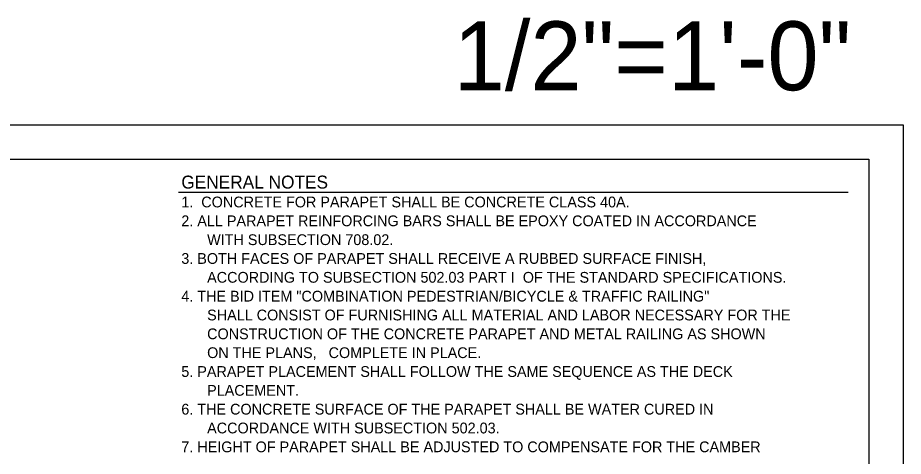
# Model space of a CAD drawing. Extents: x 0 to 68, y 0 to 47.1.
# Drawn here: x 42.27 to 68, y 34.37 to 47.11 of the extents above; entities that cross this region are included whole.
import ezdxf

# ---------------------------------------------------------------- set-up
doc = ezdxf.new("R2010")
doc.units = 0
for name, color, linetype in [('BORDER_ANNO_Cutsheet', 7, 'Continuous'), ('BRDG_ANNO_Anno-Sheet', 7, 'Continuous'), ('BRDG_ANNO_General-Notes', 7, 'Continuous')]:
    doc.layers.add(name, color=color, linetype=linetype)

msp = doc.modelspace()

# ---------------------------------------------------------------- linework, layer by layer
at = {"layer": 'BORDER_ANNO_Cutsheet'}
msp.add_lwpolyline([(0, 44), (68, 44), (68, 0), (0, 0)], close=True, dxfattribs=at)
at = {"layer": 'BRDG_ANNO_Anno-Sheet'}
msp.add_lwpolyline([(3, 43), (67, 43), (67, 1), (3, 1)], close=True, dxfattribs=at)
at = {"layer": 'BRDG_ANNO_General-Notes'}
msp.add_line((46.942, 42.037), (66.402, 42.037), dxfattribs=at)

# ---------------------------------------------------------------- texts
at = {"layer": 'BRDG_ANNO_Anno-Sheet'}
msp.add_text('1/2"=1\'-0"', height=2, dxfattribs=at).set_placement((54.934, 45))
at = {"layer": 'BRDG_ANNO_General-Notes'}
for s, height, p in [('GENERAL NOTES', 0.375, (47.021, 42.147)), ('1.  CONCRETE FOR PARAPET SHALL BE CONCRETE CLASS 40A.', 0.3125, (47.021, 41.6)), ('2. ALL PARAPET REINFORCING BARS SHALL BE EPOXY COATED IN ACCORDANCE', 0.3125, (47.021, 41.053)), ('WITH SUBSECTION 708.02.', 0.3125, (47.771, 40.506)), ('3. BOTH FACES OF PARAPET SHALL RECEIVE A RUBBED SURFACE FINISH,  ', 0.3125, (47.021, 39.96)), ('ACCORDING TO SUBSECTION 502.03 PART I  OF THE STANDARD SPECIFICATIONS.', 0.3125, (47.771, 39.413)), ('4. THE BID ITEM "COMBINATION PEDESTRIAN/BICYCLE & TRAFFIC RAILING"', 0.3125, (47.021, 38.866)), ('SHALL CONSIST OF FURNISHING ALL MATERIAL AND LABOR NECESSARY FOR THE', 0.3125, (47.771, 38.319)), ('CONSTRUCTION OF THE CONCRETE PARAPET AND METAL RAILING AS SHOWN', 0.3125, (47.771, 37.772)), ('ON THE PLANS,   COMPLETE IN PLACE.', 0.3125, (47.771, 37.225)), ('5. PARAPET PLACEMENT SHALL FOLLOW THE SAME SEQUENCE AS THE DECK', 0.3125, (47.021, 36.678)), ('PLACEMENT.', 0.3125, (47.771, 36.131)), ('6. THE CONCRETE SURFACE OF THE PARAPET SHALL BE WATER CURED IN', 0.3125, (47.021, 35.585)), ('ACCORDANCE WITH SUBSECTION 502.03.', 0.3125, (47.771, 35.038)), ('7. HEIGHT OF PARAPET SHALL BE ADJUSTED TO COMPENSATE FOR THE CAMBER', 0.3125, (47.021, 34.491))]:
    msp.add_text(s, height=height, dxfattribs=at).set_placement(p)

doc.saveas('drawing.dxf')
